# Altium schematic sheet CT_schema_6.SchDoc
size 218 x 258 mm
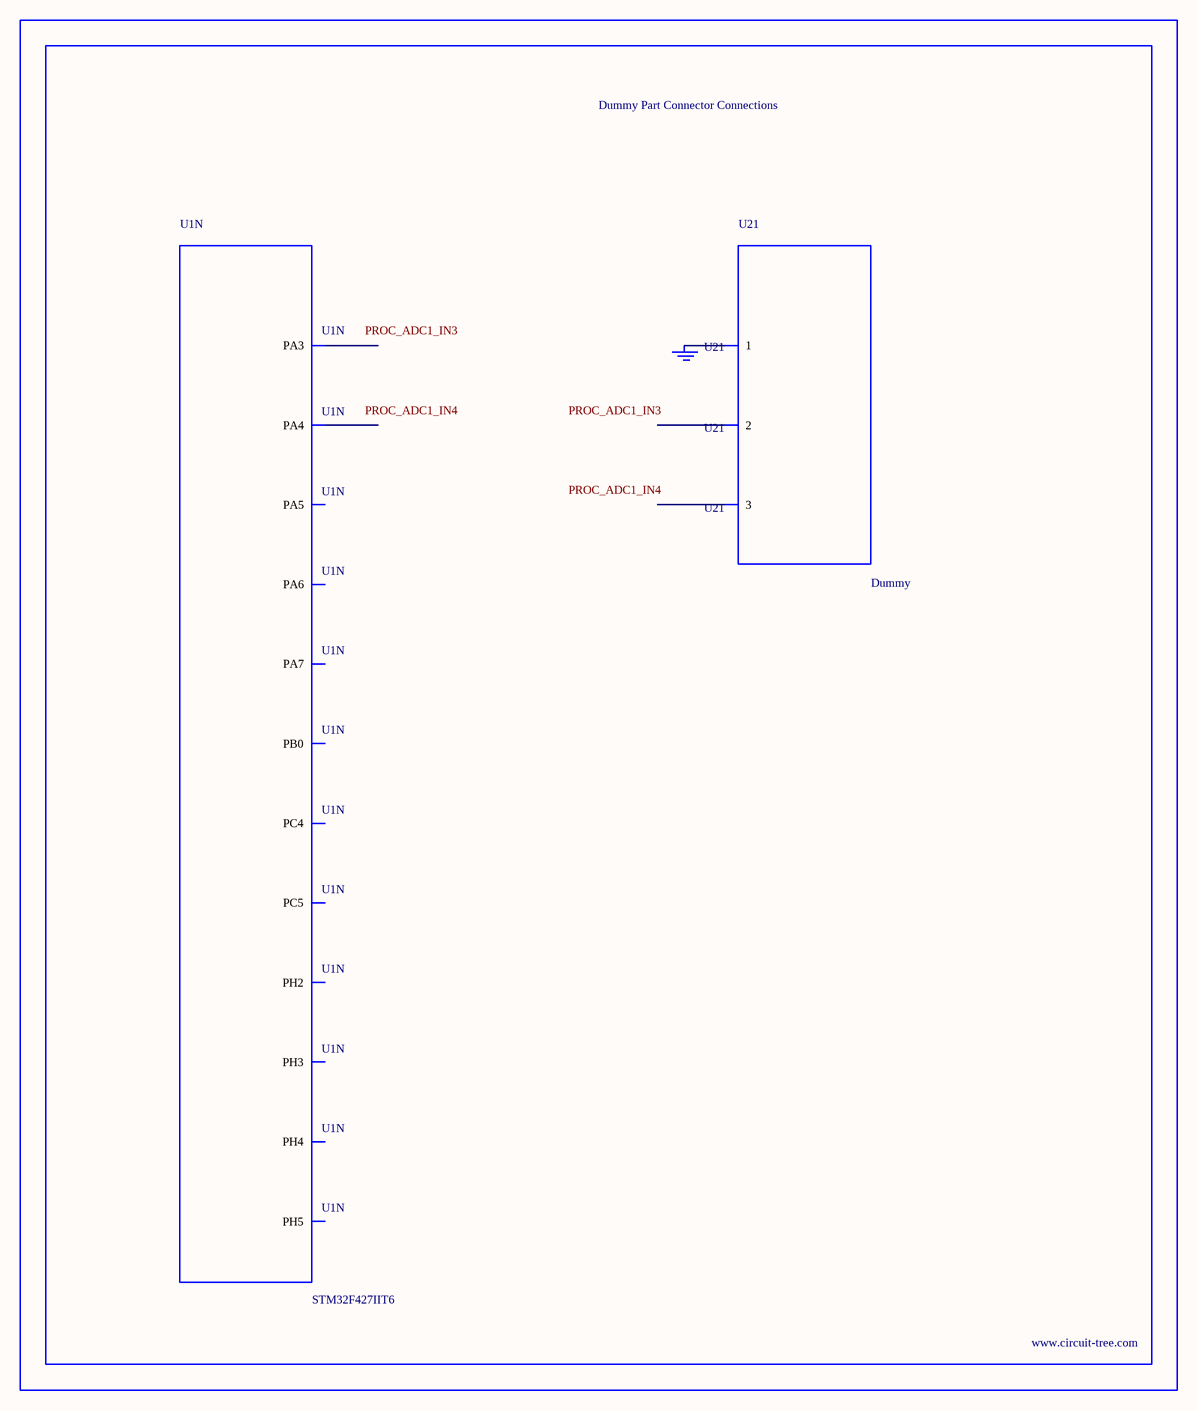
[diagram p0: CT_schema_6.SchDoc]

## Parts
BORDER5  (no value)
GND_INSTANCE_5_0  (no value)
U1  STM32F427IIT6  [LQFP176]  (part N of 14)
U21  Dummy  [DUMMY_PACKAGE_209]

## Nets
NetGND_INSTANCE_5_0_0: GND_INSTANCE_5_0.0(GND) U21.1

Not connected (* = marked no-connect by the designer): U1 43(PH2) 44(PH3) 45(PH4) 46(PH5) 47(PA3) 50(PA4) 51(PA5) 52(PA6) 53(PA7) 54(PC4) 55(PC5) 56(PB0); U21 2 3

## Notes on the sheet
- Labels drawn without touching a wire or pin: PROC_ADC1_IN3, PROC_ADC1_IN4

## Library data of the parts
BORDER5 = BORDER_PAGE5
GND_INSTANCE_5_0 = GND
